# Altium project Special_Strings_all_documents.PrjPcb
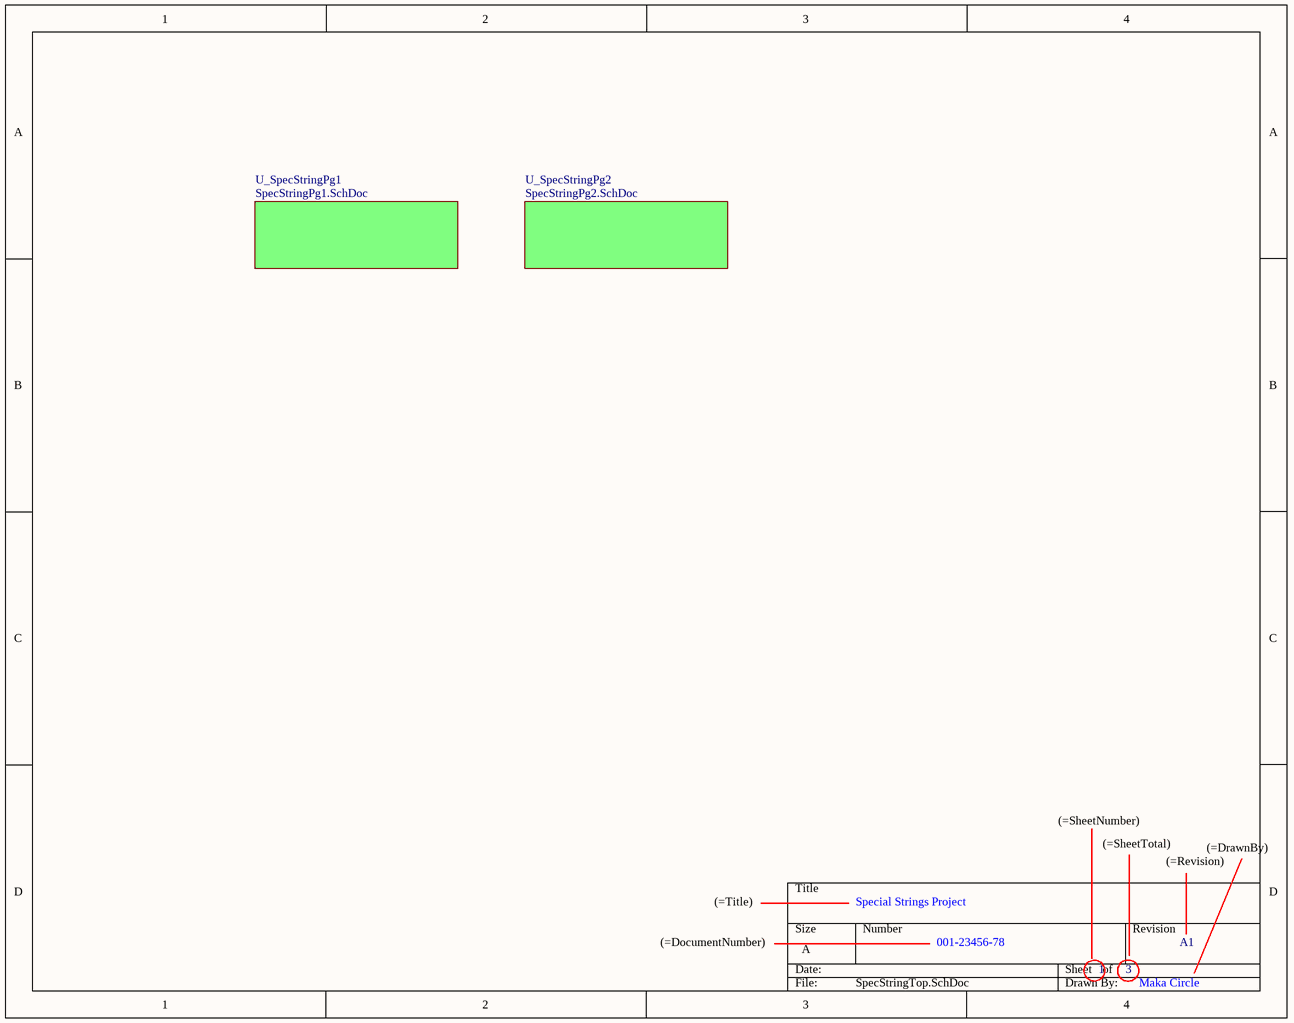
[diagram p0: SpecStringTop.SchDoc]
=Division: Robotics; =ProductPN: 12-3456-78; CageCode: 3A79-88-3
3 sheets, 15 parts. Net scope: global (net labels, ports and power ports of the same name join across sheets).
Board file: SpecString1.PcbDoc
Sheets:
  SpecStringTop.SchDoc
    U_SpecStringPg1 = SpecStringPg1.SchDoc
    U_SpecStringPg2 = SpecStringPg2.SchDoc

## Sheet SpecStringTop.SchDoc: Special Strings Project
size A; DrawnBy: Maka Circle; DocumentNumber: 001-23456-78; Revision: A1; SheetNumber: 1; SheetTotal: 3

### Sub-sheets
U_SpecStringPg1 = SpecStringPg1.SchDoc: no entries
U_SpecStringPg2 = SpecStringPg2.SchDoc: no entries

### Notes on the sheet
- (=SheetNumber)
- (=Title)
- (=SheetTotal)
- (=Revision)
- (=DrawnBy)
- (=DocumentNumber)

## Sheet SpecStringPg1.SchDoc: Special Strings Project
size A; Date: 1 Jan 2020; ApprovedBy: I. Approve; CheckedBy: Chubby Checker; Author: Iam Writer; CompanyName: A1 Widgets; DrawnBy: Maka Circle; Engineer: Robert Builder; Organization: AeroSpace; Address1: 1234 Washington St.; Address2: Suite 200; Address3: Anytown, TX 77777; Address4: U.S.A.; DocumentNumber: 001-23456-78; Revision: A1; SheetNumber: 3; SheetTotal: 4
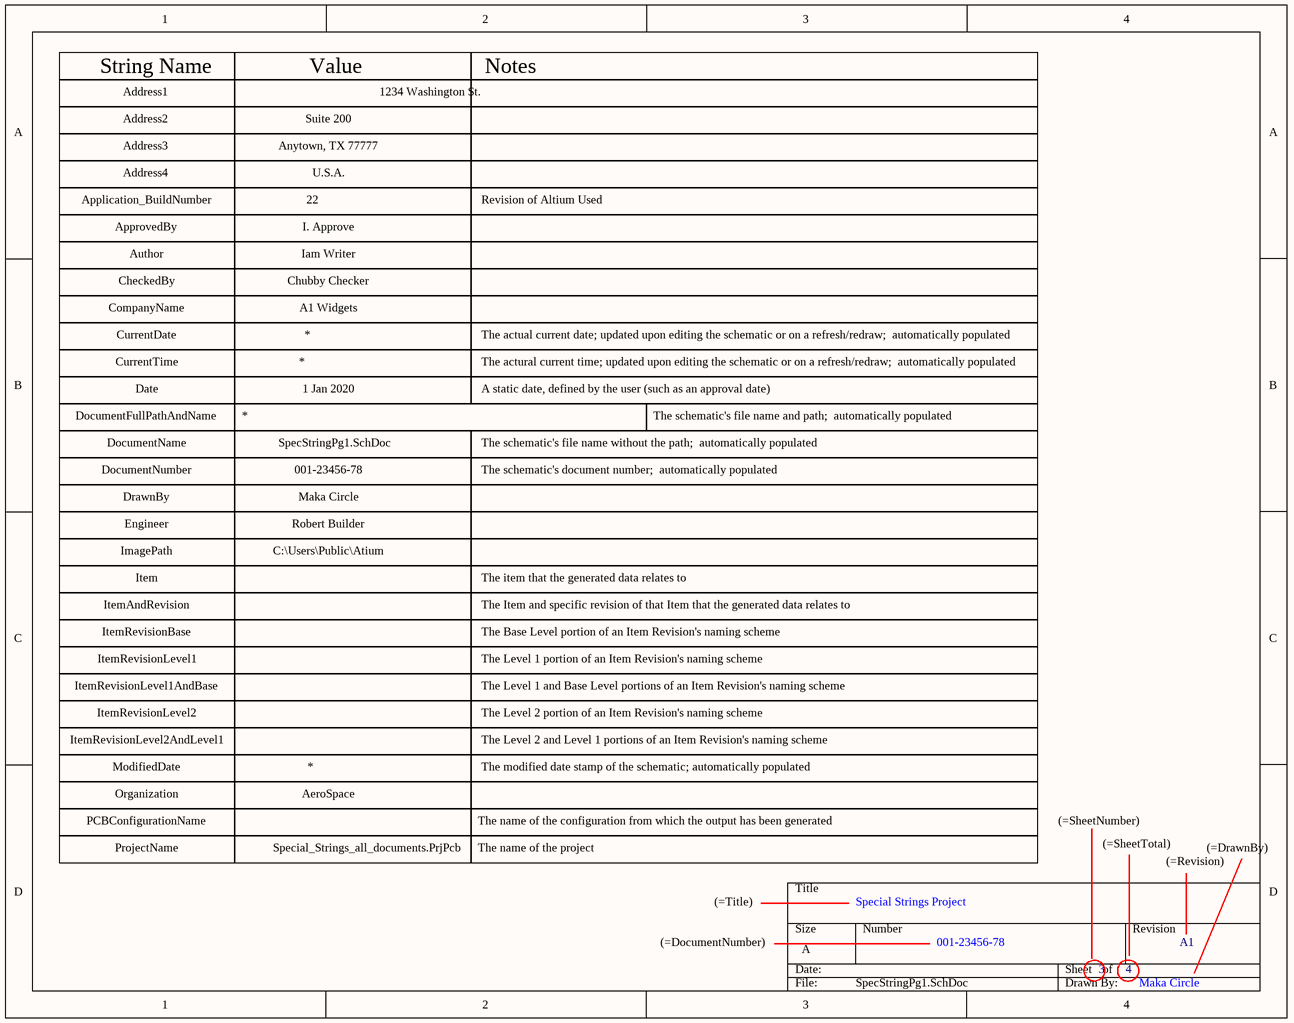
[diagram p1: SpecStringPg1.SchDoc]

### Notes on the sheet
- String Name
- Address1
- Value
- Notes
- Address2
- Address3
- Application_BuildNumber
- ApprovedBy
- Address4
- Revision of Altium Used
- CheckedBy
- Author
- CompanyName
- CurrentTime
- CurrentDate
- The actual current date; updated upon editing the schematic or on a refresh/redraw;  automatically populated
- The actural current time; updated upon editing the schematic or on a refresh/redraw;  automatically populated
- DocumentFullPathAndName
- Date
- A static date, defined by the user (such as an approval date)
- The schematic's file name and path;  automatically populated
- DocumentNumber
- DocumentName
- DrawnBy
- The schematic's file name without the path;  automatically populated
- The schematic's document number;  automatically populated
- ImagePath
- Engineer
- ItemRevisionBase
- ItemAndRevision
- Item
- The item that the generated data relates to
- The Item and specific revision of that Item that the generated data relates to
- The Base Level portion of an Item Revision's naming scheme
- ItemRevisionLevel1AndBase
- ItemRevisionLevel1
- The Level 1 portion of an Item Revision's naming scheme
- The Level 1 and Base Level portions of an Item Revision's naming scheme
- ItemRevisionLevel2AndLevel1
- ItemRevisionLevel2
- ModifiedDate
- The modified date stamp of the schematic; automatically populated
- The Level 2 portion of an Item Revision's naming scheme
- The Level 2 and Level 1 portions of an Item Revision's naming scheme
- PCBConfigurationName
- Organization
- The name of the configuration from which the output has been generated
- (=SheetNumber)
- ProjectName
- The name of the project
- (=Title)
- (=SheetTotal)
- (=Revision)
- (=DrawnBy)
- (=DocumentNumber)

## Sheet SpecStringPg2.SchDoc: Special Strings Project
size A; Date: 1 Jan 2020; ApprovedBy: I. Approve; CheckedBy: Chubby Checker; Author: Iam Writer; CompanyName: A1 Widgets; DrawnBy: Maka Circle; Engineer: Robert Builder; Organization: AeroSpace; Address1: 1234 Washington St.; Address2: Suite 200; Address3: Anytown, TX 77777; Address4: U.S.A.; DocumentNumber: 001-23456-78; Revision: A1; SheetNumber: 3; SheetTotal: 3
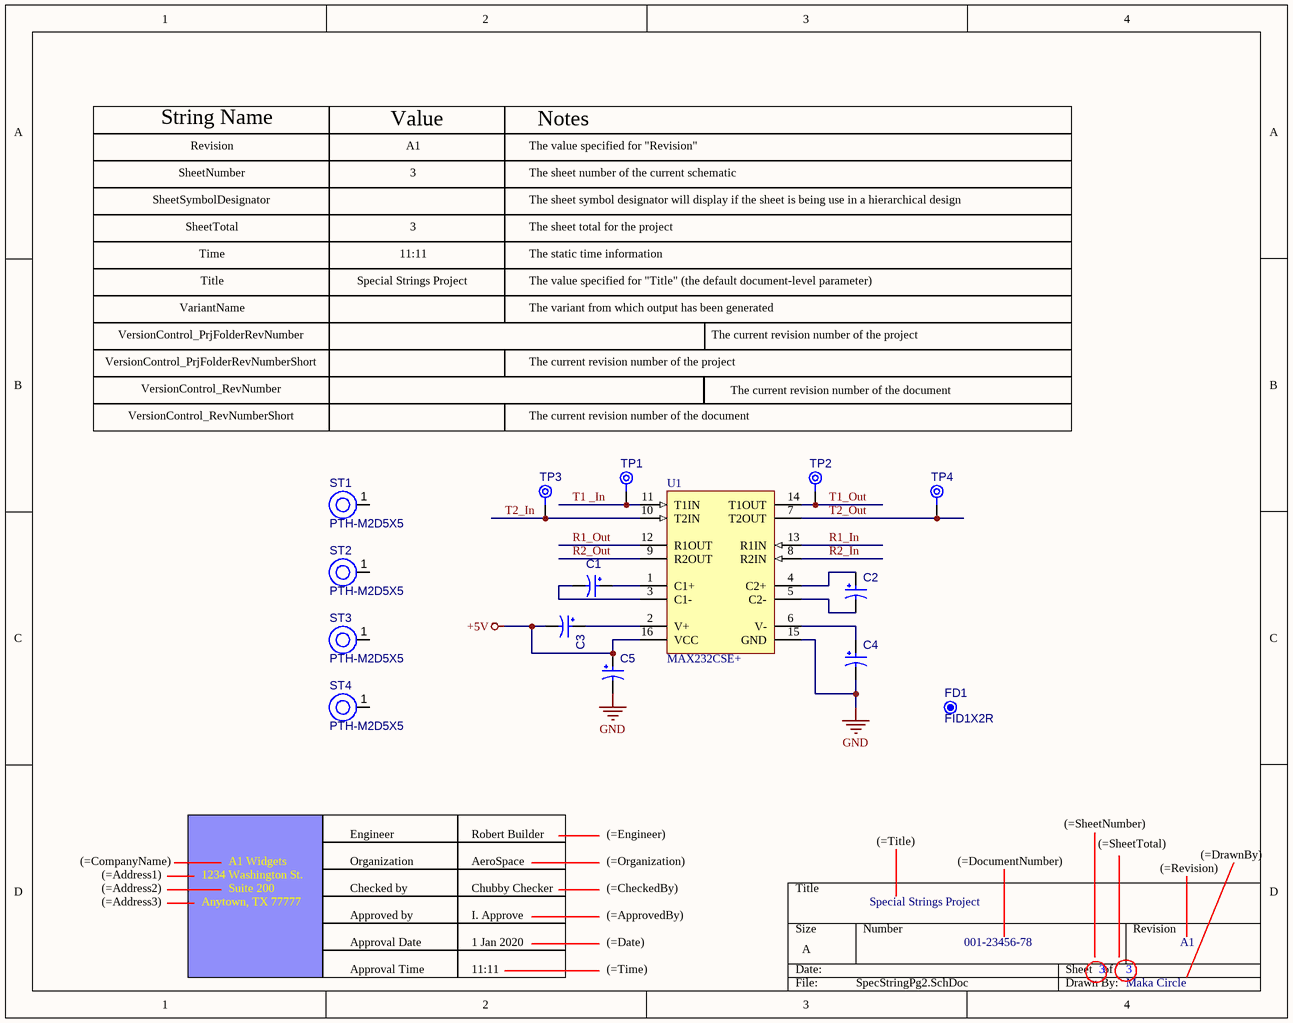
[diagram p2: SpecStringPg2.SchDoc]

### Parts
C1  KYOCERA AVX-TAJA105K035RNJ  [CAPMP3217X18-T_V]  (value not drawn)
C2  KYOCERA AVX-TAJA105K035RNJ  [CAPMP3217X18-T_V]  (value not drawn)
C3  KYOCERA AVX-TAJA105K035RNJ  [CAPMP3217X18-T_V]  (value not drawn)
C4  KYOCERA AVX-TAJA105K035RNJ  [CAPMP3217X18-T_V]  (value not drawn)
C5  KYOCERA AVX-TAJA105K035RNJ  [CAPMP3217X18-T_V]  (value not drawn)
FD1  FID1X2R  [FID1X2R]  (no BOM)
ST1  PTH-M2D5X5  [PTH-M2D5X5]
ST2  PTH-M2D5X5  [PTH-M2D5X5]
ST3  PTH-M2D5X5  [PTH-M2D5X5]
ST4  PTH-M2D5X5  [PTH-M2D5X5]
TP1  TPAD6R  [TP06R]  (value not drawn)  (no BOM)
TP2  TPAD6R  [TP06R]  (value not drawn)  (no BOM)
TP3  TPAD6R  [TP06R]  (value not drawn)  (no BOM)
TP4  TPAD6R  [TP06R]  (value not drawn)  (no BOM)
U1  MAX232CSE+  [MAXM-S16+5_M]

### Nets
+5V: C3.2 C5.1 U1.16(VCC)
GND: C4.2 C5.2 U1.15(GND)
R1_In: U1.13(R1IN)
R1_Out: U1.12(R1OUT)
R2_In: U1.8(R2IN)
R2_Out: U1.9(R2OUT)
T1 _In: TP1.1(TP) U1.11(T1IN)
T1_Out: TP2.1(TP) U1.14(T1OUT)
T2_In: TP3.1(TP) U1.10(T2IN)
T2_Out: TP4.1(TP) U1.7(T2OUT)
NetC1_1: C1.1 U1.1(C1+)
NetC1_2: C1.2 U1.3(C1-)
NetC2_1: C2.1 U1.4(C2+)
NetC2_2: C2.2 U1.5(C2-)
NetC3_1: C3.1 U1.2(V+)
NetC4_1: C4.1 U1.6(V-)

Not connected (* = marked no-connect by the designer): ST1 1(H1); ST2 1(H1); ST3 1(H1); ST4 1(H1)

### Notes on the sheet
- String Name
- Revision
- Value
- The value specified for "Revision"
- Notes
- SheetSymbolDesignator
- SheetNumber
- SheetTotal
- The sheet number of the current schematic
- The sheet total for the project
- The sheet symbol designator will display if the sheet is being use in a hierarchical design
- Time
- Title
- The static time information
- The value specified for "Title" (the default document-level parameter)
- VersionControl_PrjFolderRevNumberShort
- VersionControl_PrjFolderRevNumber
- VariantName
- The variant from which output has been generated
- The current revision number of the project
- VersionControl_RevNumberShort
- VersionControl_RevNumber
- The current revision number of the document
- Engineer
- (=Engineer)
- (=SheetNumber)
- (=CompanyName)
- (=Address1)
- (=Address2)
- (=Address3)
- Organization
- Checked by
- (=Organization)
- (=CheckedBy)
- (=Title)
- (=DocumentNumber)
- (=SheetTotal)
- (=Revision)
- (=DrawnBy)
- Approved by
- Approval Date
- Approval Time
- (=ApprovedBy)
- (=Date)
- (=Time)

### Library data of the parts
C1-C5 = CMP-001-00040-7: Standard Tantalum, 1 uF, +/- 10%, 35 V, -55 to 125 degC, 1206 (3216 Metric), RoHS, Tape and Reel; Manufacturer: AVX; Voltage Rating: 35V; ESR: 7.5Ohm; Value: 1µF
FD1 = CMP-00028-00005-1: Fiducial - Round 1x2mm
ST1-ST4 = CMP-00028-00004-1: M2 PTH (2.5mm), 5mm pad
TP1-TP4 = CMP-00028-00002-1: 0.6mm round
U1 = CMP-00024-00004-1: Multichannel RS-232 Driver/Receiver, 5 V, 0 to 70 degC, 16-Pin SOIC (S16+3), RoHS, Tube; Manufacturer: Maxim; Propagation Delay: 10us; Receivers: 2; Nominal Supply Current: 10mA; Min Supply Voltage: 4.5V; Max Supply Voltage: 5.5V; Data Rate: 120Kbps; Package Version: Rev. G, 01/2016; Nominal Supply Voltage: 5V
